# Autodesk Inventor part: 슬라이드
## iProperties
Company: 한국ATC센터
Created: 2014-10
Part Number: 슬라이드
Document SubType Name: Modeling
Designer: 한국ATC센터
Density: 7.86 g/cm^3
Material: 강, 연강
Mass: 735.303 g
Surface Area: 161.098 cm^2
Volume: 93.55 cm^3
Author: KYOUNG IL JANG
Revision Number: 1
